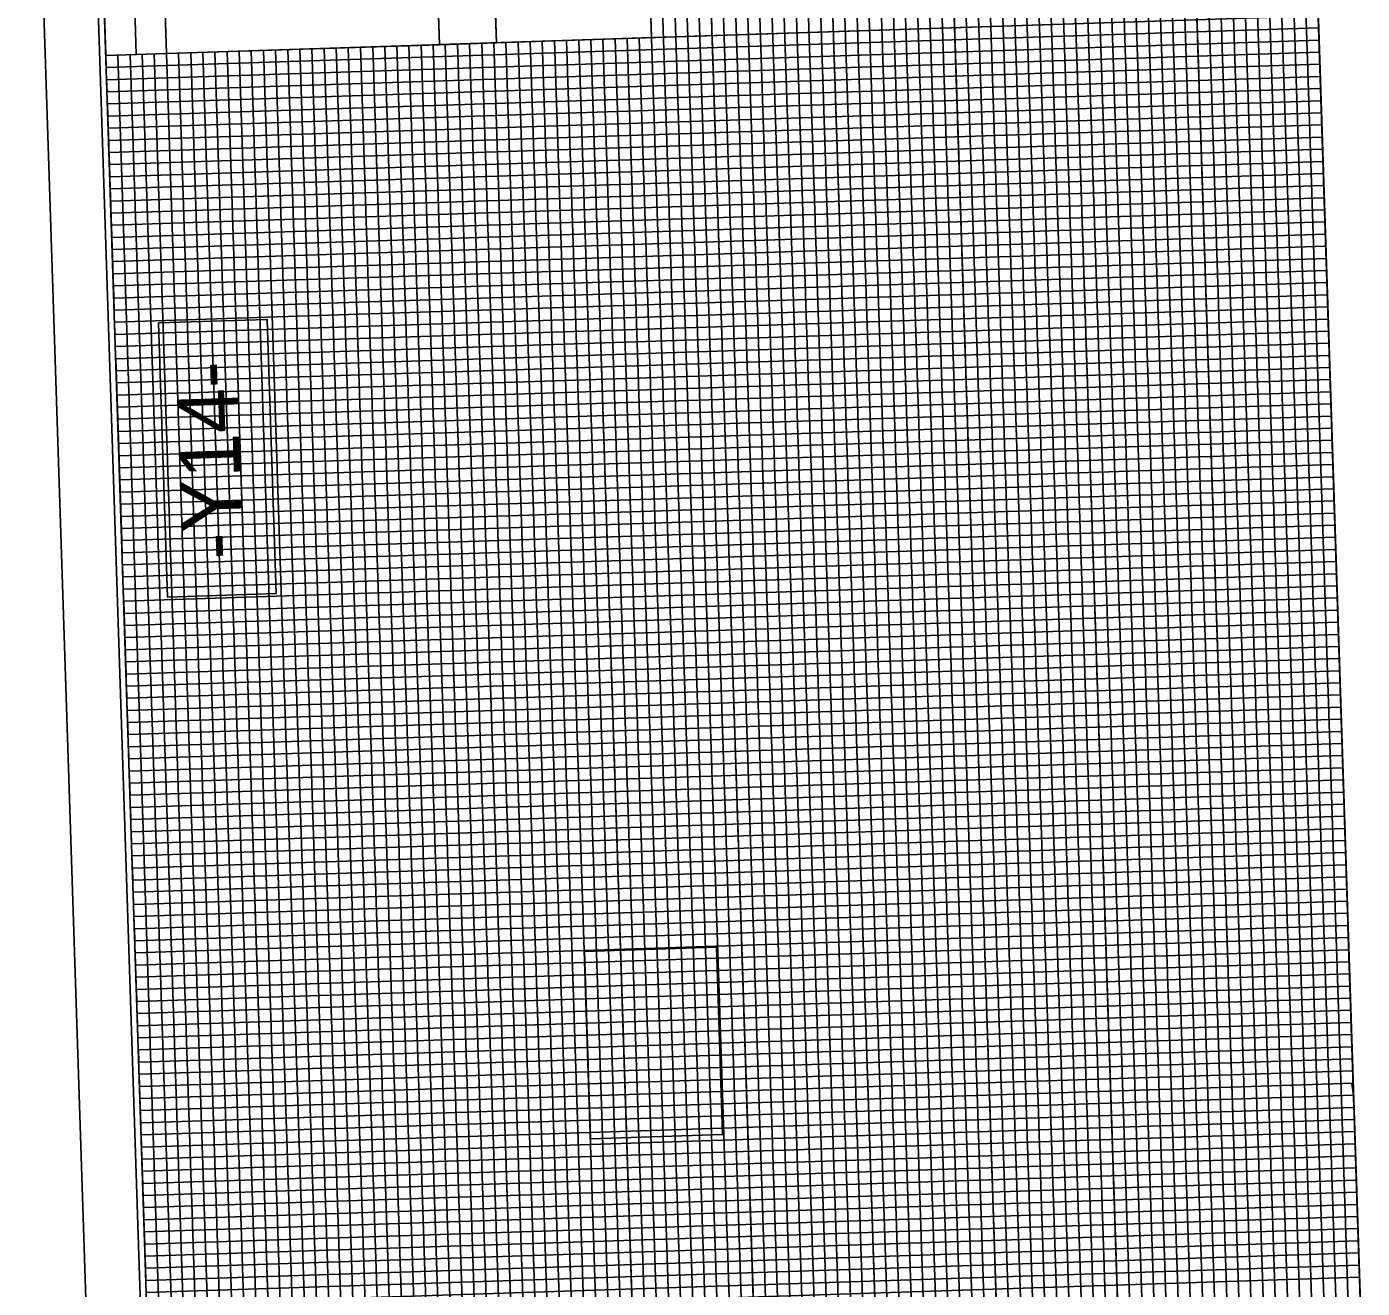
# Model space of a CAD drawing. Extents: x 1627314 to 1628469, y 762309 to 764245.
# Drawn here: x 1627314 to 1627865, y 763268 to 763788 of the extents above; entities that cross this region are included whole.
import ezdxf

# ---------------------------------------------------------------- set-up
doc = ezdxf.new("R2010")
doc.units = 0
for name, color, linetype in [('Old_Level_2', 7, 'Continuous'), ('Prop Grid Mask', 7, 'Continuous'), ('Sheet Data Field CELL', 7, 'Continuous'), ('Sheet DOT Grid CELL', 7, 'Continuous'), ('Sheet Layout Profile Border Port 1', 7, 'Continuous'), ('Sheet Plot Border Inside CELL', 7, 'Continuous'), ('Sheet Plot Border Outside CELL', 7, 'Continuous'), ('Sheet Profile CELL', 7, 'Continuous'), ('Sheet Profile Grid Major CELL', 7, 'Continuous'), ('Sheet Profile Grid Middle CELL', 7, 'Continuous'), ('Sheet Profile Grid Minor CELL', 7, 'Continuous'), ('Sheet Sticker Exception Certification CELL', 7, 'Continuous')]:
    doc.layers.add(name, color=color, linetype=linetype)

msp = doc.modelspace()

# ---------------------------------------------------------------- linework, layer by layer
at = {"layer": 'Old_Level_2'}
msp.add_lwpolyline([(1627507.79, 763781.61), (1627501.25, 763981.49), (1627565.16, 763983.58), (1627571.7, 763783.7)], close=True, dxfattribs=at)
at = {"layer": 'Prop Grid Mask'}
for points in [[(1627417.01, 763554.6), (1627413.31, 763667.62), (1627368.59, 763666.16), (1627372.29, 763553.14)], [(1627546.65, 763329.96), (1627544.12, 763407.12), (1627598.53, 763408.9), (1627601.05, 763331.74)]]:
    msp.add_lwpolyline(points, close=True, dxfattribs=at)
at = {"layer": 'Sheet DOT Grid CELL'}
for p, q in [((1627690.1, 763987.68), (1627739.13, 762488.48)), ((1627740.07, 763989.32), (1627789.11, 762490.12)), ((1627790.04, 763990.95), (1627839.08, 762491.75)), ((1627590.15, 763984.41), (1627639.19, 762485.21)), ((1627640.12, 763986.05), (1627689.16, 762486.85)), ((1627846.55, 763792.69), (1627484.3, 763780.84)), ((1627396.8, 763777.93), (1627439.29, 762478.68)), ((1627446.77, 763779.57), (1627489.27, 762480.31)), ((1627496.74, 763781.25), (1627539.24, 762481.95)), ((1627546.72, 763782.83), (1627589.21, 762483.58)), ((1627848.19, 763742.72), (1627348.46, 763726.37)), ((1627849.82, 763692.75), (1627350.09, 763676.4)), ((1627851.46, 763642.77), (1627351.73, 763626.43)), ((1627853.09, 763592.8), (1627353.36, 763576.45)), ((1627854.73, 763542.83), (1627354.99, 763526.48)), ((1627856.36, 763492.85), (1627356.63, 763476.51)), ((1627858, 763442.88), (1627358.26, 763426.53)), ((1627859.63, 763392.91), (1627359.9, 763376.56)), ((1627861.27, 763342.93), (1627361.53, 763326.59)), ((1627862.9, 763292.96), (1627363.17, 763276.61))]:
    msp.add_line(p, q, dxfattribs=at)
at = {"layer": 'Sheet Layout Profile Border Port 1'}
msp.add_lwpolyline([(1627548.65, 762532.28), (1627887.42, 762543.36), (1627841.65, 763942.61), (1627566.8, 763933.62)], dxfattribs=at)
at = {"layer": 'Sheet Plot Border Inside CELL'}
msp.add_lwpolyline([(1628446.34, 762357.53), (1628391.86, 764023.14), (1627337.33, 763988.65), (1627391.81, 762323.04)], close=True, dxfattribs=at)
at = {"layer": 'Sheet Plot Border Outside CELL'}
msp.add_lwpolyline([(1628469.21, 762345.27), (1628413.63, 764044.37), (1627314.22, 764008.4), (1627369.79, 762309.31)], close=True, dxfattribs=at)
at = {"layer": 'Sheet Profile CELL'}
for p, q in [((1627889.05, 762493.39), (1627840.02, 763992.59)), ((1627359.37, 763776.71), (1627352.83, 763976.65))]:
    msp.add_line(p, q, dxfattribs=at)
for points in [[(1627340.28, 763976.24), (1627389.32, 762477.04), (1628438.76, 762511.37), (1628389.72, 764010.57)], [(1627346.82, 763776.3), (1627340.28, 763976.24), (1627365.32, 763977.06), (1627371.86, 763777.12)], [(1627371.86, 763777.12), (1627368.59, 763877.11), (1627481.03, 763880.79), (1627484.3, 763780.79)]]:
    msp.add_lwpolyline(points, close=True, dxfattribs=at)
at = {"layer": 'Sheet Profile Grid Major CELL'}
for points in [[(1627640.12, 763986.05), (1627689.16, 762486.85), (1627739.13, 762488.48), (1627690.1, 763987.68)], [(1627740.07, 763989.32), (1627789.11, 762490.12), (1627789.11, 762490.12), (1627839.08, 762491.75), (1627790.04, 763990.95)], [(1627546.71, 763782.88), (1627589.21, 762483.58), (1627639.19, 762485.21), (1627590.15, 763984.41)], [(1627864.53, 763242.99), (1627862.9, 763292.96), (1627363.17, 763276.61), (1627361.53, 763326.59), (1627861.27, 763342.93), (1627859.63, 763392.91), (1627359.9, 763376.56), (1627358.26, 763426.53), (1627858, 763442.88), (1627856.36, 763492.85), (1627356.63, 763476.51), (1627354.99, 763526.48), (1627854.73, 763542.83), (1627853.09, 763592.8), (1627353.36, 763576.45), (1627351.73, 763626.43), (1627851.46, 763642.77), (1627849.82, 763692.75), (1627350.09, 763676.4), (1627348.46, 763726.37), (1627848.19, 763742.72), (1627846.55, 763792.69), (1627346.82, 763776.35), (1627345.96, 763802.63)], [(1627439.29, 762478.68), (1627396.79, 763777.98)], [(1627446.77, 763779.62), (1627489.27, 762480.31), (1627539.24, 762481.95), (1627496.74, 763781.25)]]:
    msp.add_lwpolyline(points, dxfattribs=at)
at = {"layer": 'Sheet Profile Grid Middle CELL'}
msp.add_line((1627414.31, 762477.86), (1627371.81, 763777.11), dxfattribs=at)
for points in [[(1627615.14, 763985.23), (1627664.17, 762486.03), (1627714.15, 762487.67), (1627665.11, 763986.86)], [(1627715.08, 763988.5), (1627764.12, 762489.3), (1627814.09, 762490.94), (1627765.06, 763990.13)], [(1627815.03, 763991.77), (1627864.07, 762492.57)], [(1627863.72, 763267.97), (1627862.08, 763317.95), (1627362.35, 763301.6), (1627360.72, 763351.57), (1627860.45, 763367.92), (1627858.81, 763417.89), (1627359.08, 763401.55), (1627357.45, 763451.52), (1627857.18, 763467.87), (1627855.54, 763517.84), (1627355.81, 763501.49), (1627354.18, 763551.47), (1627853.91, 763567.81), (1627852.28, 763617.79), (1627352.54, 763601.44), (1627350.91, 763651.41), (1627850.64, 763667.76), (1627849.01, 763717.73), (1627349.27, 763701.39), (1627347.64, 763751.36), (1627847.37, 763767.71), (1627845.74, 763817.68), (1627570.88, 763808.69)], [(1627521.73, 763782.02), (1627564.23, 762482.76), (1627614.2, 762484.4), (1627570.88, 763808.69)], [(1627421.78, 763778.8), (1627464.28, 762479.49), (1627514.25, 762481.13), (1627471.75, 763780.43)]]:
    msp.add_lwpolyline(points, dxfattribs=at)
at = {"layer": 'Sheet Profile Grid Minor CELL'}
for p, q in [((1627676.74, 763937.22), (1627722.51, 762537.97)), ((1627727.51, 762538.13), (1627681.74, 763937.38)), ((1627686.73, 763937.55), (1627732.5, 762538.29)), ((1627742.5, 762538.62), (1627696.73, 763937.87)), ((1627701.73, 763938.04), (1627747.49, 762538.78)), ((1627752.49, 762538.95), (1627706.72, 763938.2)), ((1627711.72, 763938.36), (1627757.49, 762539.11)), ((1627767.48, 762539.44), (1627721.71, 763938.69)), ((1627726.71, 763938.85), (1627772.48, 762539.6)), ((1627731.71, 763939.02), (1627777.48, 762539.76)), ((1627736.71, 763939.18), (1627782.48, 762539.93)), ((1627792.47, 762540.25), (1627746.7, 763939.51)), ((1627751.7, 763939.67), (1627797.47, 762540.42)), ((1627802.47, 762540.58), (1627756.7, 763939.83)), ((1627761.69, 763940), (1627807.46, 762540.75)), ((1627817.46, 762541.07), (1627771.69, 763940.32)), ((1627776.69, 763940.49), (1627822.45, 762541.24)), ((1627827.45, 762541.4), (1627781.68, 763940.65)), ((1627786.68, 763940.81), (1627832.45, 762541.56)), ((1627842.44, 762541.89), (1627796.67, 763941.14)), ((1627801.67, 763941.3), (1627847.44, 762542.05)), ((1627852.44, 762542.22), (1627806.67, 763941.47)), ((1627811.67, 763941.63), (1627857.44, 762542.38)), ((1627867.43, 762542.71), (1627821.66, 763941.96)), ((1627826.66, 763942.12), (1627872.43, 762542.87)), ((1627877.42, 762543.03), (1627831.66, 763942.29)), ((1627576.79, 763933.95), (1627622.56, 762534.7)), ((1627627.56, 762534.86), (1627581.79, 763934.11)), ((1627586.79, 763934.28), (1627632.56, 762535.02)), ((1627642.55, 762535.35), (1627596.78, 763934.6)), ((1627601.78, 763934.77), (1627647.55, 762535.51)), ((1627652.55, 762535.68), (1627606.78, 763934.93)), ((1627611.77, 763935.09), (1627657.54, 762535.84)), ((1627667.54, 762536.17), (1627621.77, 763935.42)), ((1627626.77, 763935.58), (1627672.53, 762536.33)), ((1627677.53, 762536.5), (1627631.76, 763935.75)), ((1627636.76, 763935.91), (1627682.53, 762536.66)), ((1627692.52, 762536.99), (1627646.75, 763936.24)), ((1627651.75, 763936.4), (1627697.52, 762537.15)), ((1627702.52, 762537.31), (1627656.75, 763936.56)), ((1627661.75, 763936.73), (1627707.52, 762537.48)), ((1627717.51, 762537.8), (1627671.74, 763937.05)), ((1627556.71, 763783.16), (1627597.57, 762533.88)), ((1627602.57, 762534.04), (1627561.71, 763783.33)), ((1627481.75, 763780.71), (1627522.61, 762531.43)), ((1627486.75, 763780.92), (1627527.61, 762531.59)), ((1627491.74, 763781.09), (1627532.61, 762531.75)), ((1627542.6, 762532.08), (1627501.74, 763781.41)), ((1627506.74, 763781.58), (1627547.6, 762532.25)), ((1627552.6, 762532.41), (1627511.73, 763781.69)), ((1627531.72, 763782.34), (1627572.59, 762533.06)), ((1627577.59, 762533.23), (1627536.72, 763782.51)), ((1627392.68, 762527.18), (1627351.82, 763776.51)), ((1627356.82, 763776.67), (1627398.03, 762527.35)), ((1627402.68, 762527.5), (1627361.81, 763776.84))]:
    msp.add_line(p, q, dxfattribs=at)
for points in [[(1627836.65, 763942.45), (1627882.42, 762543.2)], [(1627566.71, 763783.49), (1627607.57, 762534.21), (1627617.56, 762534.53), (1627571.79, 763933.79)], [(1627850.15, 763682.75), (1627849.99, 763687.75), (1627350.25, 763671.4), (1627349.93, 763681.4), (1627849.66, 763697.74), (1627849.5, 763702.74), (1627349.76, 763686.39), (1627349.6, 763691.39), (1627849.33, 763707.74), (1627849.17, 763712.74), (1627349.44, 763696.39), (1627349.11, 763706.38), (1627848.84, 763722.73), (1627848.68, 763727.73), (1627348.95, 763711.38), (1627348.78, 763716.38), (1627848.52, 763732.72), (1627848.35, 763737.72), (1627348.62, 763721.38), (1627348.29, 763731.37), (1627848.03, 763747.72), (1627847.86, 763752.71), (1627348.13, 763736.37), (1627347.97, 763741.37), (1627847.7, 763757.71), (1627847.53, 763762.71), (1627347.8, 763746.36), (1627347.48, 763756.36), (1627847.21, 763772.7), (1627847.04, 763777.7), (1627347.31, 763761.35), (1627347.15, 763766.35), (1627846.88, 763782.7), (1627846.72, 763787.7), (1627346.98, 763771.35), (1627346.66, 763781.34)], [(1627381.8, 763777.44), (1627422.67, 762528.16), (1627427.67, 762528.32), (1627386.8, 763777.65)], [(1627391.8, 763777.82), (1627432.66, 762528.49), (1627442.66, 762528.81), (1627401.79, 763778.14)], [(1627406.79, 763778.31), (1627447.65, 762528.98), (1627452.65, 762529.14), (1627411.79, 763778.47)], [(1627416.78, 763778.63), (1627457.65, 762529.3), (1627467.64, 762529.63), (1627426.78, 763778.96)], [(1627431.78, 763779.13), (1627472.64, 762529.79), (1627477.64, 762529.96), (1627436.77, 763779.29)], [(1627441.77, 763779.45), (1627482.64, 762530.12), (1627492.63, 762530.45), (1627451.77, 763779.78)], [(1627456.86, 763779.95), (1627497.72, 762530.71), (1627502.62, 762530.87), (1627461.76, 763780.11)], [(1627466.76, 763780.27), (1627507.62, 762530.94), (1627517.62, 762531.26), (1627476.75, 763780.6)], [(1627516.73, 763781.85), (1627557.6, 762532.57), (1627567.59, 762532.9), (1627526.73, 763782.18)], [(1627541.72, 763782.67), (1627582.58, 762533.39), (1627592.58, 762533.72), (1627551.71, 763783)], [(1627366.81, 763777), (1627407.68, 762527.67), (1627417.67, 762528), (1627376.81, 763777.33)], [(1627860.12, 763377.91), (1627360.39, 763361.57), (1627360.23, 763366.57), (1627859.96, 763382.91), (1627859.79, 763387.91), (1627360.06, 763371.56), (1627359.73, 763381.56), (1627859.47, 763397.9), (1627859.3, 763402.9), (1627359.57, 763386.55), (1627359.41, 763391.55), (1627859.14, 763407.9), (1627858.98, 763412.9), (1627359.24, 763396.55), (1627358.92, 763406.54), (1627858.65, 763422.89), (1627858.49, 763427.89), (1627358.75, 763411.54), (1627358.59, 763416.54), (1627858.32, 763432.88), (1627858.16, 763437.88), (1627358.43, 763421.54), (1627358.1, 763431.53), (1627857.83, 763447.88), (1627857.67, 763452.87), (1627357.94, 763436.53), (1627357.77, 763441.53), (1627857.51, 763457.87), (1627857.34, 763462.87), (1627357.61, 763446.52), (1627357.28, 763456.52), (1627857.02, 763472.86), (1627856.85, 763477.86), (1627357.12, 763461.51), (1627356.96, 763466.51), (1627856.69, 763482.86), (1627856.53, 763487.86), (1627356.79, 763471.51), (1627356.47, 763481.5), (1627856.2, 763497.85), (1627856.03, 763502.85), (1627356.3, 763486.5), (1627356.14, 763491.5), (1627855.87, 763507.84), (1627855.71, 763512.84), (1627355.98, 763496.5), (1627355.65, 763506.49), (1627855.38, 763522.84), (1627855.22, 763527.83), (1627355.48, 763511.49), (1627355.32, 763516.49), (1627855.05, 763532.83), (1627854.89, 763537.83), (1627355.16, 763521.48), (1627354.83, 763531.48), (1627854.56, 763547.82), (1627854.4, 763552.82), (1627354.67, 763536.47), (1627354.5, 763541.47), (1627854.24, 763557.82), (1627854.07, 763562.82), (1627354.34, 763546.47), (1627354.01, 763556.46), (1627853.75, 763572.81), (1627853.58, 763577.81), (1627353.85, 763561.46), (1627353.69, 763566.46), (1627853.42, 763582.8), (1627853.26, 763587.8), (1627353.52, 763571.46), (1627353.2, 763581.45), (1627852.93, 763597.8), (1627852.77, 763602.79), (1627353.03, 763586.45), (1627352.87, 763591.45), (1627852.6, 763607.79), (1627852.44, 763612.79), (1627352.71, 763596.44), (1627352.38, 763606.44), (1627852.11, 763622.78), (1627851.95, 763627.78), (1627352.22, 763611.43), (1627352.05, 763616.43), (1627851.78, 763632.78), (1627851.62, 763637.78), (1627351.89, 763621.43), (1627351.56, 763631.42), (1627851.29, 763647.77), (1627851.13, 763652.77), (1627351.4, 763636.42), (1627351.23, 763641.42), (1627850.97, 763657.76), (1627850.8, 763662.76), (1627351.07, 763646.42), (1627350.74, 763656.41), (1627850.48, 763672.76), (1627850.31, 763677.75), (1627350.58, 763661.41), (1627350.42, 763666.41), (1627850.15, 763682.75)], [(1627363.49, 763266.62), (1627863.23, 763282.97), (1627863.06, 763287.96), (1627363.33, 763271.62), (1627363, 763281.61), (1627862.74, 763297.96), (1627862.57, 763302.95), (1627362.84, 763286.61), (1627362.68, 763291.61), (1627862.41, 763307.95), (1627862.25, 763312.95), (1627362.51, 763296.6), (1627362.19, 763306.6), (1627861.92, 763322.94), (1627861.76, 763327.94), (1627362.02, 763311.59), (1627361.86, 763316.59), (1627861.59, 763332.94), (1627861.43, 763337.94), (1627361.7, 763321.59), (1627361.37, 763331.58), (1627861.1, 763347.93), (1627860.4, 763352.61), (1627860.94, 763352.93), (1627361.21, 763336.58), (1627361.04, 763341.58), (1627860.78, 763357.93), (1627860.61, 763362.92), (1627360.88, 763346.58), (1627360.55, 763356.57), (1627860.28, 763372.92), (1627860.12, 763377.91)], [(1627363.82, 763256.62), (1627863.55, 763272.97), (1627863.39, 763277.97), (1627363.66, 763261.62)]]:
    msp.add_lwpolyline(points, dxfattribs=at)
at = {"layer": 'Sheet Sticker Exception Certification CELL'}
for p, q in [((1627501.25, 763981.49), (1627507.79, 763781.56)), ((1627501.25, 763981.49), (1627507.79, 763781.56)), ((1627484.3, 763780.79), (1627477.76, 763980.72)), ((1627484.3, 763780.79), (1627477.76, 763980.72)), ((1627507.79, 763781.56), (1627484.3, 763780.79)), ((1627507.79, 763781.56), (1627484.3, 763780.79))]:
    msp.add_line(p, q, dxfattribs=at)

# ---------------------------------------------------------------- texts
at = {"layer": 'Sheet Data Field CELL'}
msp.add_text('-Y14-', height=25, rotation=91.8735, dxfattribs=at).set_placement((1627403.48, 763569))

doc.saveas('drawing.dxf')
